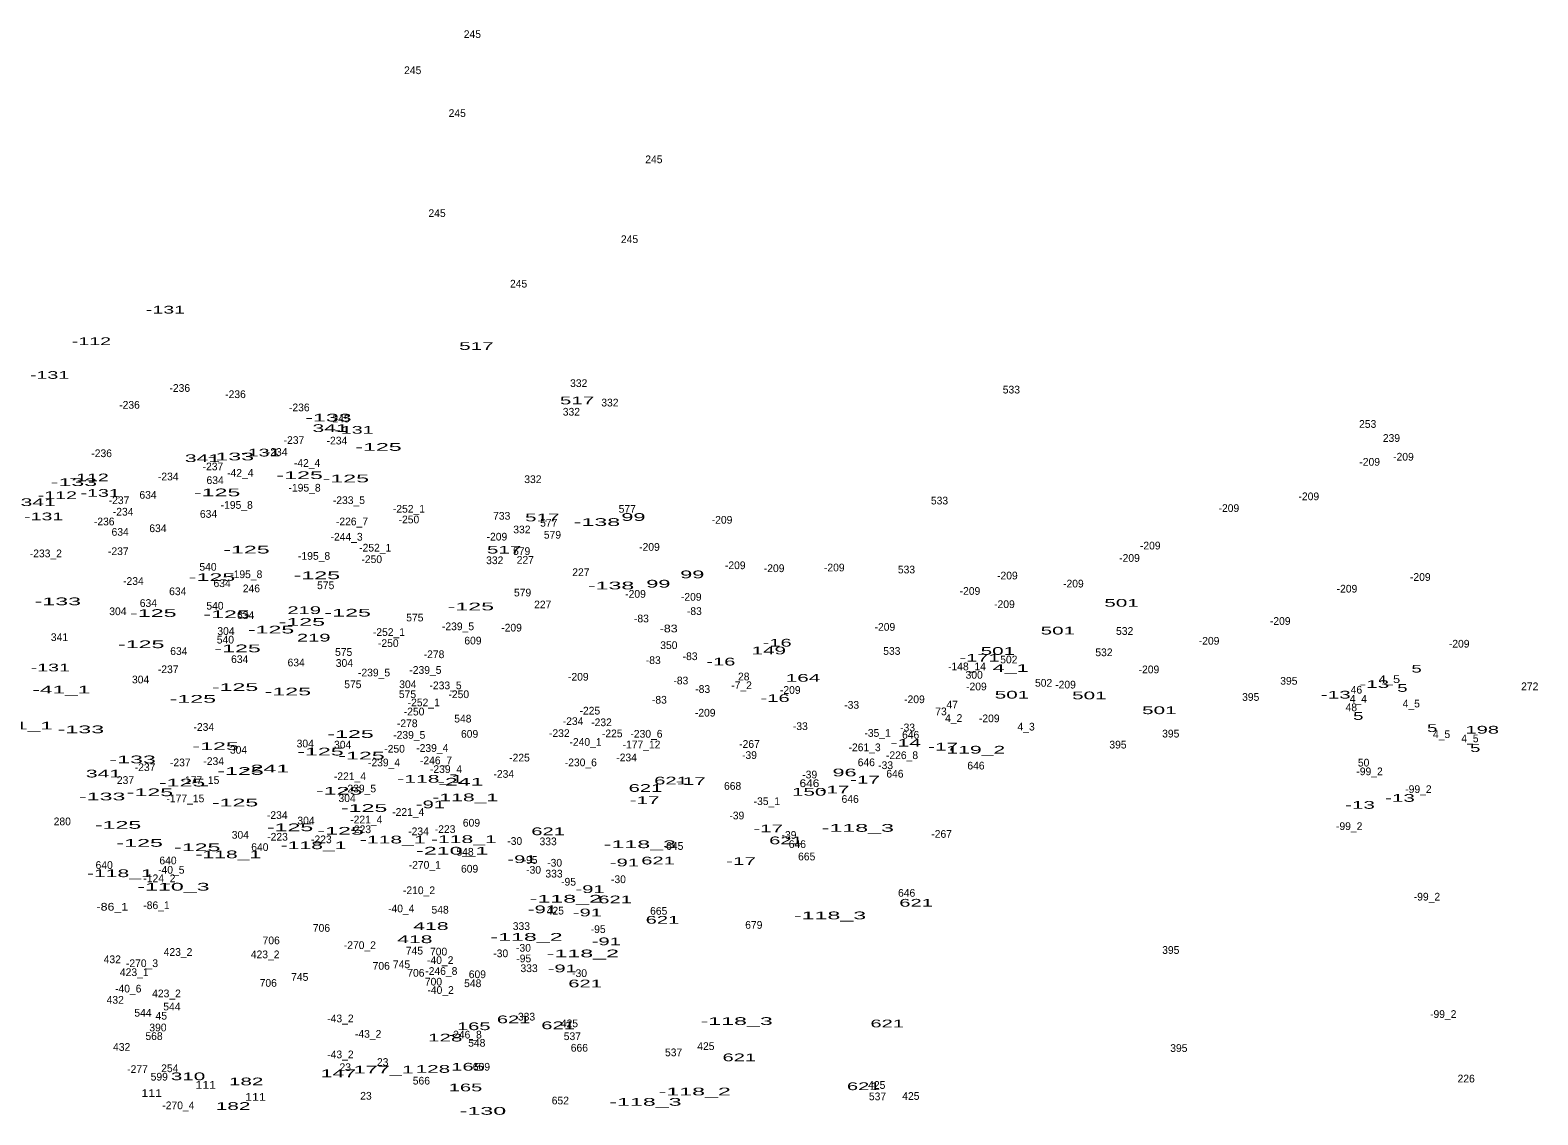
# Model space of a CAD drawing. Extents: x -658595 to -655205, y -1004347 to -1000147.
# Drawn here: x -656879 to -656097, y -1000817 to -1000254 of the extents above; entities that cross this region are included whole.
import ezdxf
from ezdxf.enums import TextEntityAlignment as Align

# ---------------------------------------------------------------- set-up
doc = ezdxf.new("R2010")
doc.units = 0
doc.header["$LTSCALE"] = 1.6
doc.layers.add('24', color=7, linetype='Continuous')

msp = doc.modelspace()

# ---------------------------------------------------------------- texts
at = {"layer": '24'}
for s, p in [('245', (-656650.031, -1000258.14)), ('245', (-656680.971, -1000276.89)), ('245', (-656657.871, -1000299.12)), ('245', (-656555.891, -1000323.1)), ('245', (-656668.331, -1000351)), ('245', (-656568.531, -1000364.52)), ('245', (-656626.061, -1000387.62)), ('-236', (-656801.78, -1000441.71)), ('-236', (-656772.87, -1000444.95)), ('332', (-656594.877, -1000439.2)), ('533', (-656370.497, -1000442.55)), ('-236', (-656827.83, -1000450.46)), ('-236', (-656739.78, -1000451.79)), ('332', (-656598.677, -1000454.04)), ('332', (-656578.707, -1000449.29)), ('245', (-656718.121, -1000457.57)), ('253', (-656185.707, -1000460.38)), ('-237', (-656742.551, -1000468.73)), ('-234', (-656720.269, -1000468.99)), ('239', (-656173.403, -1000467.67)), ('-236', (-656842.29, -1000475.58)), ('-234', (-656751.269, -1000474.89)), ('-209', (-656167.174, -1000477.38)), ('-237', (-656784.581, -1000482.43)), ('-42_4', (-656735.741, -1000480.63)), ('-209', (-656184.674, -1000480.04)), ('-234', (-656807.749, -1000487.63)), ('634', (-656783.437, -1000489.54)), ('-42_4', (-656770.391, -1000485.76)), ('-195_8', (-656737.052, -1000493.45)), ('332', (-656618.647, -1000489.05)), ('-237', (-656833.271, -1000499.93)), ('634', (-656818.237, -1000497.15)), ('-233_5', (-656714.052, -1000499.92)), ('533', (-656407.777, -1000500.12)), ('-209', (-656216.244, -1000497.93)), ('-234', (-656831.149, -1000505.9)), ('634', (-656786.857, -1000507.05)), ('-195_8', (-656772.232, -1000502.39)), ('-252_1', (-656682.936, -1000504.39)), ('733', (-656634.803, -1000508.03)), ('577', (-656569.719, -1000504.42)), ('-209', (-656257.704, -1000504.02)), ('-236', (-656840.96, -1000510.96)), ('634', (-656832.687, -1000516.37)), ('634', (-656813.107, -1000514.47)), ('-226_7', (-656712.454, -1000510.95)), ('-250', (-656682.939, -1000509.92)), ('332', (-656624.347, -1000515.11)), ('577', (-656610.419, -1000511.65)), ('-209', (-656520.534, -1000510.1)), ('-244_3', (-656715.251, -1000518.89)), ('-252_1', (-656700.406, -1000524.56)), ('-209', (-656637.304, -1000518.85)), ('579', (-656608.498, -1000517.86)), ('-209', (-656558.194, -1000524.17)), ('-209', (-656298.484, -1000523.48)), ('-233_2', (-656871.232, -1000527.52)), ('-237', (-656833.641, -1000526.38)), ('-195_8', (-656732.112, -1000528.83)), ('-250', (-656702.219, -1000530.54)), ('332', (-656638.427, -1000531.09)), ('579', (-656624.468, -1000526.33)), ('227', (-656622.573, -1000530.89)), ('-209', (-656309.244, -1000529.89)), ('540', (-656787.145, -1000534.5)), ('-195_8', (-656767.292, -1000538.34)), ('227', (-656593.753, -1000537.27)), ('-209', (-656513.694, -1000533.69)), ('-209', (-656493.534, -1000535.22)), ('-209', (-656462.344, -1000534.84)), ('533', (-656424.897, -1000535.89)), ('-209', (-656372.574, -1000539.02)), ('-209', (-656158.424, -1000539.76)), ('-234', (-656825.829, -1000541.86)), ('634', (-656802.827, -1000547.19)), ('634', (-656779.817, -1000543)), ('246', (-656764.627, -1000545.68)), ('575', (-656726.093, -1000544.06)), ('579', (-656623.998, -1000547.83)), ('-209', (-656391.974, -1000547.01)), ('-209', (-656338.344, -1000543.2)), ('-209', (-656196.454, -1000545.84)), ('634', (-656818.047, -1000553.28)), ('540', (-656783.525, -1000554.67)), ('227', (-656613.533, -1000554.01)), ('-209', (-656565.424, -1000548.53)), ('-209', (-656536.514, -1000550.06)), ('-209', (-656374.094, -1000553.86)), ('304', (-656833.875, -1000557.55)), ('634', (-656767.647, -1000559.55)), ('575', (-656679.873, -1000560.8)), ('-83', (-656562.365, -1000561.29)), ('-83', (-656534.905, -1000557.45)), ('-209', (-656231.074, -1000562.59)), ('341', (-656864.16, -1000570.97)), ('304', (-656777.825, -1000567.81)), ('-252_1', (-656693.296, -1000568.35)), ('-239_5', (-656657.468, -1000565.36)), ('-209', (-656629.704, -1000566.04)), ('-209', (-656436.094, -1000565.66)), ('532', (-656311.747, -1000567.78)), ('634', (-656802.257, -1000578.2)), ('540', (-656778.105, -1000572.26)), ('575', (-656716.773, -1000578.68)), ('-250', (-656693.629, -1000574.07)), ('609', (-656649.742, -1000572.75)), ('350', (-656548.131, -1000575.13)), ('533', (-656432.497, -1000578.13)), ('532', (-656322.497, -1000578.83)), ('-209', (-656267.964, -1000572.86)), ('-209', (-656138.264, -1000574.38)), ('634', (-656770.687, -1000582.39)), ('634', (-656741.397, -1000584.1)), ('304', (-656716.395, -1000584.37)), ('-278', (-656669.911, -1000579.85)), ('-83', (-656556.215, -1000582.9)), ('-83', (-656537.115, -1000580.88)), ('-148_14', (-656393.527, -1000586.15)), ('502', (-656371.821, -1000582.57)), ('304', (-656822.085, -1000592.93)), ('-237', (-656807.781, -1000587.63)), ('-239_5', (-656701.018, -1000589.33)), ('-239_5', (-656674.388, -1000588)), ('-209', (-656595.084, -1000591.53)), ('-83', (-656541.915, -1000593.46)), ('28', (-656509.287, -1000591.38)), ('300', (-656389.775, -1000590.51)), ('502', (-656353.781, -1000594.67)), ('-209', (-656299.154, -1000587.7)), ('395', (-656226.603, -1000593.62)), ('575', (-656712.013, -1000595.42)), ('575', (-656683.683, -1000600.56)), ('304', (-656683.495, -1000595.41)), ('-233_5', (-656663.932, -1000595.99)), ('-250', (-656657.079, -1000600.59)), ('-83', (-656530.585, -1000597.88)), ('-7_2', (-656510.439, -1000595.94)), ('-209', (-656485.164, -1000598.38)), ('-209', (-656388.634, -1000596.55)), ('-209', (-656342.414, -1000595.59)), ('395', (-656246.373, -1000601.99)), ('46', (-656191.547, -1000598.23)), ('272', (-656101.663, -1000596.48)), ('-250', (-656680.259, -1000609.57)), ('-252_1', (-656675.256, -1000604.84)), ('-225', (-656589.095, -1000609.11)), ('-83', (-656553.045, -1000603.45)), ('-209', (-656529.284, -1000610.17)), ('-33', (-656453.315, -1000606.11)), ('-209', (-656420.774, -1000603.2)), ('73', (-656407.003, -1000609.48)), ('47', (-656401.197, -1000605.96)), ('48', (-656194.201, -1000607.37)), ('4_4', (-656190.555, -1000602.95)), ('4_5', (-656163.111, -1000605.42)), ('-234', (-656789.309, -1000617.57)), ('-278', (-656683.811, -1000615.66)), ('548', (-656654.961, -1000613.24)), ('-234', (-656597.799, -1000614.53)), ('-232', (-656583.055, -1000615.14)), ('-33', (-656479.945, -1000617.15)), ('-33', (-656424.315, -1000617.81)), ('4_2', (-656400.421, -1000612.94)), ('-209', (-656381.974, -1000613.1)), ('4_3', (-656362.861, -1000617.39)), ('304', (-656736.695, -1000626.16)), ('-239_5', (-656682.758, -1000621.67)), ('609', (-656651.462, -1000621.15)), ('-232', (-656604.925, -1000620.76)), ('-240_1', (-656591.344, -1000625.33)), ('-225', (-656577.495, -1000620.91)), ('-230_6', (-656559.742, -1000621.1)), ('-267', (-656506.325, -1000626.39)), ('-35_1', (-656439.886, -1000620.67)), ('646', (-656422.723, -1000621.63)), ('395', (-656287.843, -1000621.01)), ('4_5', (-656147.421, -1000621.31)), ('4_5', (-656132.681, -1000623.5)), ('304', (-656771.305, -1000629.4)), ('304', (-656717.295, -1000626.73)), ('-250', (-656690.379, -1000628.87)), ('-239_4', (-656670.822, -1000628.47)), ('-225', (-656625.605, -1000633.46)), ('-234', (-656570.039, -1000633.37)), ('-177_12', (-656562.31, -1000626.66)), ('-39', (-656506.31, -1000632.14)), ('-261_3', (-656446.622, -1000628.12)), ('-226_8', (-656427.198, -1000632.22)), ('395', (-656315.223, -1000626.72)), ('-237', (-656819.761, -1000638.43)), ('-237', (-656801.501, -1000635.96)), ('-234', (-656784.179, -1000635.27)), ('-239_4', (-656695.832, -1000635.98)), ('-246_7', (-656668.878, -1000634.9)), ('-239_4', (-656663.692, -1000639.41)), ('-234', (-656633.749, -1000641.93)), ('-230_6', (-656593.782, -1000635.94)), ('646', (-656445.733, -1000635.9)), ('-33', (-656435.725, -1000637.41)), ('646', (-656430.893, -1000641.8)), ('646', (-656388.863, -1000637.61)), ('-99_2', (-656184.743, -1000640.59)), ('50', (-656187.821, -1000636.07)), ('237', (-656829.943, -1000645.11)), ('-177_15', (-656791.06, -1000645.12)), ('-221_4', (-656713.52, -1000643.13)), ('-239_5', (-656708.288, -1000649.49)), ('668', (-656515.068, -1000648.15)), ('-39', (-656475.09, -1000642.24)), ('-99_2', (-656159.403, -1000649.81)), ('-177_15', (-656798.86, -1000654.63)), ('304', (-656715.015, -1000654.51)), ('-35_1', (-656497.316, -1000656.07)), ('646', (-656454.103, -1000654.93)), ('-234', (-656751.229, -1000663.28)), ('-221_4', (-656683.28, -1000661.68)), ('-39', (-656512.88, -1000663.48)), ('280', (-656862.701, -1000666.55)), ('304', (-656736.315, -1000666.11)), ('-221_4', (-656705.05, -1000665.58)), ('-223', (-656707.915, -1000670.63)), ('-234', (-656677.959, -1000671.71)), ('-223', (-656664.175, -1000670.55)), ('609', (-656650.502, -1000667.25)), ('-267', (-656406.675, -1000673.06)), ('-99_2', (-656195.303, -1000669.01)), ('304', (-656770.355, -1000673.53)), ('640', (-656760.241, -1000679.88)), ('-223', (-656751.075, -1000674.52)), ('-223', (-656728.355, -1000675.86)), ('-30', (-656628.069, -1000676.72)), ('333', (-656610.737, -1000676.9)), ('645', (-656545.077, -1000679.31)), ('-39', (-656485.84, -1000673.57)), ('646', (-656481.483, -1000678.33)), ('640', (-656807.881, -1000686.82)), ('548', (-656653.821, -1000682.3)), ('-95', (-656620.12, -1000686.53)), ('-30', (-656607.359, -1000688)), ('665', (-656476.638, -1000684.74)), ('640', (-656840.971, -1000689.2)), ('-124_2', (-656812.33, -1000696.07)), ('-40_5', (-656806.161, -1000691.66)), ('-270_1', (-656674.706, -1000689.11)), ('609', (-656651.462, -1000691.11)), ('-30', (-656618.279, -1000691.66)), ('333', (-656607.687, -1000693.64)), ('-30', (-656574.269, -1000696.56)), ('-210_2', (-656677.7, -1000702.29)), ('-95', (-656600.15, -1000697.86)), ('646', (-656424.813, -1000703.63)), ('-86_1', (-656813.852, -1000710.05)), ('-40_4', (-656686.915, -1000711.71)), ('548', (-656666.751, -1000712.36)), ('-99_2', (-656154.983, -1000705.6)), ('425', (-656607.001, -1000712.85)), ('665', (-656553.388, -1000712.96)), ('679', (-656504.073, -1000720.24)), ('706', (-656728.292, -1000721.8)), ('333', (-656624.607, -1000720.85)), ('-95', (-656584.79, -1000722.44)), ('423_2', (-656802.67, -1000734.29)), ('423_2', (-656757.5, -1000735.53)), ('706', (-656754.352, -1000728.27)), ('-270_2', (-656708.372, -1000730.75)), ('745', (-656680.067, -1000733.6)), ('700', (-656667.541, -1000734.09)), ('-30', (-656635.319, -1000734.99)), ('-30', (-656623.529, -1000732.13)), ('395', (-656287.833, -1000733.26)), ('432', (-656836.761, -1000738.09)), ('-270_3', (-656821.362, -1000740.12)), ('706', (-656697.292, -1000741.49)), ('745', (-656686.777, -1000740.69)), ('-40_2', (-656666.701, -1000738.51)), ('-95', (-656623.39, -1000737.62)), ('333', (-656620.617, -1000742.72)), ('423_1', (-656825.383, -1000744.76)), ('706', (-656755.872, -1000750.34)), ('745', (-656739.547, -1000747.25)), ('706', (-656679.322, -1000745.11)), ('700', (-656670.201, -1000749.69)), ('-246_8', (-656666.122, -1000744.17)), ('548', (-656649.831, -1000750.51)), ('609', (-656647.432, -1000745.85)), ('-30', (-656594.429, -1000745.26)), ('432', (-656835.241, -1000759.12)), ('-40_6', (-656828.496, -1000753.29)), ('423_2', (-656808.66, -1000755.79)), ('-40_2', (-656666.501, -1000754.02)), ('544', (-656820.876, -1000765.82)), ('544', (-656805.856, -1000762.58)), ('-99_2', (-656146.533, -1000766.49)), ('390', (-656813.087, -1000773.47)), ('45', (-656811.361, -1000767.38)), ('-43_2', (-656718.457, -1000768.76)), ('333', (-656621.947, -1000767.83)), ('425', (-656599.691, -1000771.33)), ('568', (-656815.113, -1000777.93)), ('-43_2', (-656704.077, -1000776.77)), ('-246_8', (-656653.472, -1000777.16)), ('548', (-656647.741, -1000781.43)), ('537', (-656598.163, -1000777.99)), ('432', (-656831.911, -1000783.56)), ('-43_2', (-656718.457, -1000787.43)), ('666', (-656594.533, -1000783.98)), ('537', (-656545.673, -1000786.37)), ('425', (-656528.941, -1000783.12)), ('395', (-656283.653, -1000784.13)), ('-277', (-656823.695, -1000795.05)), ('254', (-656806.951, -1000794.62)), ('23', (-656715.957, -1000794.05)), ('23', (-656696.547, -1000791.39)), ('609', (-656645.322, -1000793.84)), ('599', (-656812.408, -1000798.99)), ('566', (-656676.468, -1000801.05)), ('425', (-656440.321, -1000803.29)), ('226', (-656134.643, -1000799.96)), ('-270_4', (-656802.506, -1000813.85)), ('23', (-656705.207, -1000808.89)), ('652', (-656604.413, -1000811.35)), ('537', (-656439.923, -1000809.2)), ('425', (-656422.631, -1000809))]:
    msp.add_text(s, height=4, dxfattribs=at).set_placement(p, align=Align.CENTER)
for s, width, p in [('-131', 1.9, (-656809.197, -1000401.09)), ('-112', 1.9, (-656847.587, -1000417.44)), ('517', 2, (-656647.943, -1000419.95)), ('-131', 1.9, (-656869.287, -1000434.96)), ('517', 2, (-656595.723, -1000448.19)), ('-133', 2.25, (-656724.681, -1000457.09)), ('341', 2.05, (-656723.803, -1000462.53)), ('-131', 1.9, (-656711.437, -1000463.43)), ('-133', 2.25, (-656775.271, -1000477.25)), ('-131', 1.9, (-656759.747, -1000475.22)), ('-125', 2.25, (-656698.711, -1000472.31)), ('341', 2.05, (-656789.983, -1000478.13)), ('-133', 2.25, (-656856.661, -1000490.57)), ('-112', 1.9, (-656848.747, -1000488.12)), ('-125', 2.25, (-656739.601, -1000486.95)), ('-125', 2.25, (-656715.641, -1000488.66)), ('341', 2.05, (-656875.183, -1000500.96)), ('-112', 1.9, (-656865.257, -1000497.34)), ('-131', 1.9, (-656843.047, -1000496.15)), ('-125', 2.25, (-656782.391, -1000495.89)), ('-131', 1.9, (-656872.337, -1000508.33)), ('517', 2, (-656613.773, -1000508.89)), ('99', 2.1, (-656566.521, -1000508.64)), ('-138', 2.25, (-656585.431, -1000511.26)), ('-125', 2.25, (-656767.181, -1000525.57)), ('517', 2, (-656633.543, -1000525.6)), ('-125', 2.25, (-656785.051, -1000539.84)), ('-125', 2.25, (-656730.661, -1000538.89)), ('99', 2.1, (-656536.001, -1000538.41)), ('-138', 2.25, (-656578.111, -1000544.17)), ('99', 2.1, (-656553.581, -1000543.26)), ('-133', 2.25, (-656865.031, -1000552.4)), ('-125', 2.25, (-656650.821, -1000555.06)), ('501', 2, (-656313.364, -1000553.18)), ('-125', 2.25, (-656815.481, -1000558.48)), ('-125', 2.25, (-656777.481, -1000559.11)), ('-125', 2.25, (-656738.461, -1000563.05)), ('219', 1.95, (-656737.253, -1000556.96)), ('-125', 2.25, (-656714.691, -1000558.29)), ('-125', 2.25, (-656754.431, -1000567.05)), ('219', 1.95, (-656732.313, -1000571.23)), ('-83', 1.2, (-656548.23, -1000566.48)), ('501', 2, (-656346.384, -1000567.59)), ('-125', 2.25, (-656821.761, -1000574.66)), ('-125', 2.25, (-656771.781, -1000576.8)), ('149', 2, (-656496.318, -1000577.89)), ('-16', 1.95, (-656491.965, -1000573.86)), ('501', 2, (-656377.494, -1000578.15)), ('-131', 1.9, (-656868.907, -1000586.71)), ('-16', 1.95, (-656521.165, -1000583.66)), ('-171', 1.95, (-656386.971, -1000581.68)), ('4_1', 2.1, (-656370.865, -1000586.99)), ('164', 2, (-656478.558, -1000592.09)), ('4_5', 1.25, (-656174.451, -1000592.77)), ('5', 1.8, (-656160.351, -1000587.33)), ('-41_1', 2.2, (-656863.193, -1000598.19)), ('-125', 2.25, (-656794.981, -1000602.98)), ('-125', 2.25, (-656773.111, -1000596.89)), ('-125', 2.25, (-656745.721, -1000599.17)), ('-16', 1.95, (-656493.015, -1000602.59)), ('501', 2, (-656370.194, -1000600.82)), ('501', 2, (-656330.064, -1000601.2)), ('-13', 2, (-656202.261, -1000600.82)), ('-13', 2, (-656182.291, -1000595.31)), ('5', 1.8, (-656167.691, -1000597.32)), ('501', 2, (-656293.774, -1000608.89)), ('-41_1', 2.2, (-656882.613, -1000616.86)), ('5', 1.8, (-656190.581, -1000611.88)), ('5', 1.8, (-656152.281, -1000618.15)), ('-133', 2.25, (-656853.051, -1000618.8)), ('-125', 2.25, (-656713.201, -1000621.23)), ('-14', 2.05, (-656425.276, -1000625.76)), ('198', 1.95, (-656126.313, -1000619)), ('-125', 2.25, (-656783.191, -1000627.52)), ('-125', 2.25, (-656728.801, -1000630.33)), ('-125', 2.25, (-656707.501, -1000632.42)), ('-17', 2, (-656405.915, -1000627.77)), ('119_2', 2.05, (-656388.96, -1000629.36)), ('5', 1.8, (-656129.941, -1000628.52)), ('341', 2.05, (-656841.333, -1000641.74)), ('-133', 2.25, (-656826.231, -1000634.39)), ('-125', 2.25, (-656770.261, -1000640.41)), ('-241', 2.25, (-656757.056, -1000639.13)), ('96', 2.1, (-656457.031, -1000641.17)), ('-125', 2.25, (-656800.591, -1000646.41)), ('-118_1', 2.05, (-656671.944, -1000644.47)), ('-241', 2.25, (-656656.256, -1000645.98)), ('621', 1.95, (-656560.273, -1000649.22)), ('621', 1.95, (-656547.013, -1000645.37)), ('-17', 2, (-656536.755, -1000645.65)), ('646', 1.15, (-656475.231, -1000646.75)), ('-17', 2, (-656446.415, -1000644.89)), ('-133', 2.25, (-656842.021, -1000653.61)), ('-125', 2.25, (-656817.231, -1000651.45)), ('-125', 2.25, (-656773.111, -1000656.77)), ('-125', 2.25, (-656719.101, -1000650.68)), ('-91', 1.95, (-656671.775, -1000657.72)), ('-118_1', 2.05, (-656653.704, -1000654.08)), ('-17', 2, (-656560.715, -1000655.54)), ('150', 2, (-656475.344, -1000651.2)), ('-17', 2, (-656462.205, -1000650.03)), ('-13', 2, (-656168.981, -1000654.38)), ('-125', 2.25, (-656706.171, -1000659.62)), ('-13', 2, (-656189.711, -1000657.99)), ('-125', 2.25, (-656833.781, -1000668.38)), ('-125', 2.25, (-656744.581, -1000669.62)), ('-125', 2.25, (-656718.341, -1000671.42)), ('621', 1.95, (-656610.753, -1000671.69)), ('-17', 2, (-656496.625, -1000670.19)), ('-118_3', 2.25, (-656450.117, -1000669.93)), ('-125', 2.25, (-656822.561, -1000677.7)), ('-125', 2.25, (-656792.701, -1000679.98)), ('-118_1', 2.05, (-656732.384, -1000678.94)), ('-118_1', 2.05, (-656691.334, -1000675.97)), ('-118_1', 2.05, (-656654.464, -1000675.78)), ('-118_3', 2.25, (-656563.157, -1000678.4)), ('621', 1.95, (-656487.403, -1000676.4)), ('-118_1', 2.05, (-656776.594, -1000683.65)), ('-210_1', 2.25, (-656660.504, -1000681.75)), ('-91', 1.95, (-656624.345, -1000686.15)), ('-91', 1.95, (-656571.165, -1000687.87)), ('621', 1.95, (-656553.733, -1000686.87)), ('-17', 2, (-656510.705, -1000687.12)), ('-118_1', 2.05, (-656832.844, -1000693.44)), ('-110_3', 2.25, (-656805.044, -1000700.43)), ('-91', 1.95, (-656589.015, -1000701.7)), ('-86_1', 1.2, (-656836.74, -1000710.82)), ('-91', 1.95, (-656613.695, -1000712.17)), ('-118_2', 2.25, (-656601.567, -1000706.67)), ('621', 1.95, (-656576.003, -1000707.03)), ('621', 1.95, (-656419.903, -1000708.76)), ('-91', 1.95, (-656590.365, -1000713.8)), ('621', 1.95, (-656551.433, -1000717.6)), ('-118_3', 2.25, (-656464.547, -1000715.32)), ('418', 2.05, (-656679.873, -1000727.69)), ('418', 2.05, (-656671.513, -1000720.84)), ('-118_2', 2.25, (-656621.947, -1000726.48)), ('-118_2', 2.25, (-656592.727, -1000735.04)), ('-91', 1.95, (-656580.575, -1000728.79)), ('-91', 1.95, (-656603.415, -1000742.81)), ('621', 1.95, (-656591.553, -1000750.63)), ('165', 1.95, (-656649.313, -1000772.82)), ('621', 1.95, (-656628.613, -1000769.26)), ('621', 1.95, (-656605.573, -1000772.34)), ('-118_3', 2.25, (-656512.987, -1000770.13)), ('621', 1.95, (-656434.883, -1000771.38)), ('128', 2, (-656664.117, -1000778.71)), ('621', 1.95, (-656511.593, -1000788.96)), ('147', 2.05, (-656719.538, -1000797.23)), ('177_1', 2.1, (-656696.005, -1000795.28)), ('128', 2, (-656670.487, -1000794.96)), ('165', 1.95, (-656652.263, -1000793.82)), ('310', 2, (-656797.484, -1000798.79)), ('111', 1.2, (-656788.29, -1000803.21)), ('182', 2, (-656767.347, -1000801.45)), ('165', 1.95, (-656653.593, -1000804.56)), ('621', 1.95, (-656447.083, -1000803.94)), ('111', 1.2, (-656816.34, -1000807.49)), ('111', 1.2, (-656762.52, -1000809.48)), ('-118_3', 2.25, (-656560.277, -1000812.05)), ('-118_2', 2.25, (-656534.717, -1000806.67)), ('182', 2, (-656774.107, -1000814.2)), ('-130', 2.25, (-656644.557, -1000816.72))]:
    msp.add_text(s, height=4, dxfattribs=dict(at, width=width)).set_placement(p, align=Align.CENTER)

doc.saveas('drawing.dxf')
